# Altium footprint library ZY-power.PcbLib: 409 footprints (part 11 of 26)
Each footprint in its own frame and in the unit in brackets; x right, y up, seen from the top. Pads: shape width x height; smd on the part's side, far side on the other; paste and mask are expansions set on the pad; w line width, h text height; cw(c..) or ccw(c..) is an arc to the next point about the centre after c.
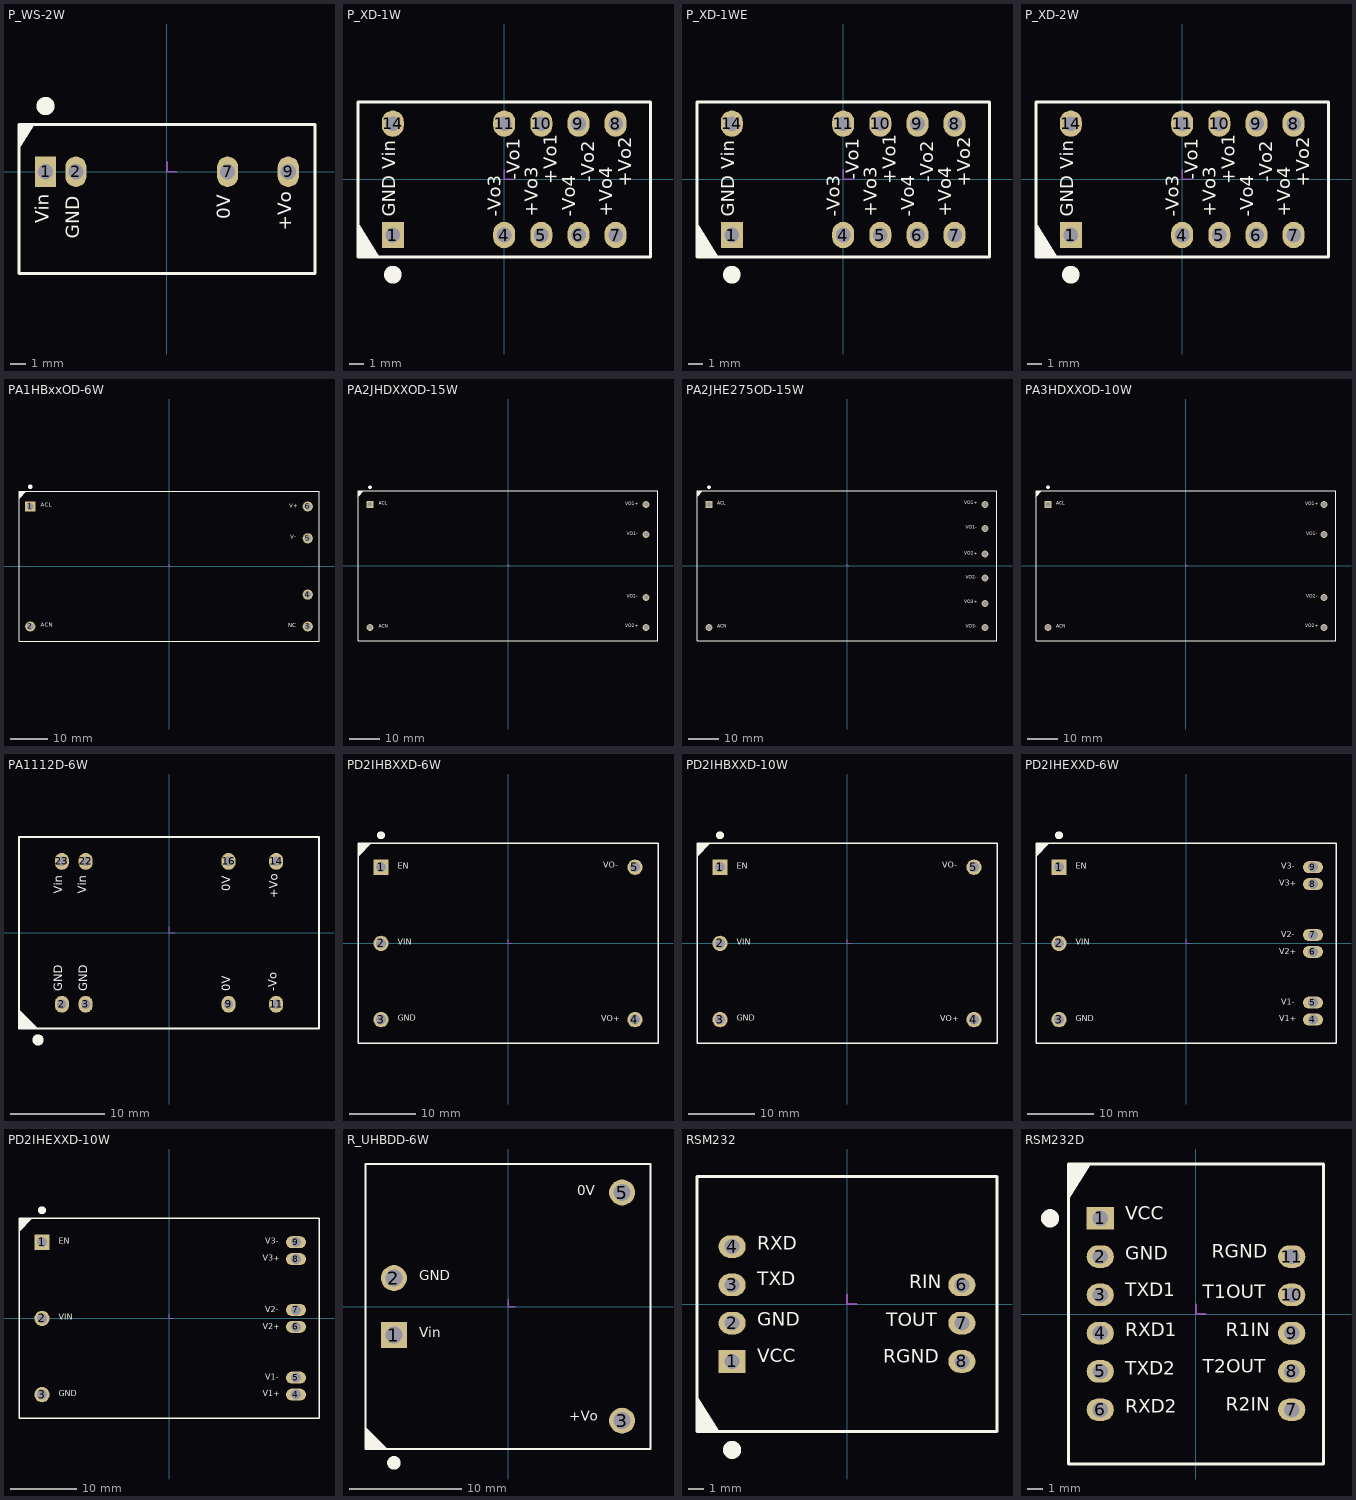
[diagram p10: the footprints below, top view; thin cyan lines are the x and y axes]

## P_WS-2W [mm]
height 12.5
pads (4):
  rect 1.4x2 hole 1: 1(-8,0)
  oval 1.4x2 hole 1: 2(-6,0) 7(4,0) 9(8,0)
Top Overlay:
  circle w1: c-8,4.325 r0.1
  region: -9.75,1.514 -9.75,3.1 -8.756,3.1
  lines w0.2: -9.75,-6.7 9.75,-6.7 9.75,3.1 -9.75,3.1 -9.75,-6.7
  text "Vin" at -7.492,-3.407 h1.52
  text "GND" at -5.475,-4.421 h1.52
  text "0V" at 4.48,-3.137 h1.52
  text "+Vo" at 8.5,-3.875 h1.52
Mechanical 15:
  lines w0.127: 0,0.635 0,0 0.635,0
3D body "zhenjao01.stp": height 8.36, standoff -4.08, extent 7.3,-1.48 8.7,0.12
3D body "zhenjao01.stp": height 8.36, standoff -4.08, extent 3.3,-1.48 4.7,0.12
3D body "zhenjao01.stp": height 8.36, standoff -4.08, extent -6.7,-1.48 -5.3,0.12
3D body "zhenjao01.stp": height 8.36, standoff -4.08, extent -8.7,-1.48 -7.3,0.12
3D body: height 12.5, standoff 0, extent -9.75,-6.7 9.75,3.1

## P_XD-1W [mm]
height 8.5
pads (10):
  rect 1.5x1.8 hole 1: 1(-7.62,-3.81)
  oval 1.5x1.8 hole 1: 4(0,-3.81) 5(2.54,-3.81) 6(5.08,-3.81) 7(7.62,-3.81) 8(7.62,3.81) 9(5.08,3.81) 10(2.54,3.81) 11(0,3.81) 14(-7.62,3.81)
Top Overlay:
  circle w1: c-7.62,-6.525 r0.1
  region: -10,-2.97 -10,-5.3 -8.54,-5.3
  lines w0.2: -10,-5.3 10,-5.3 10,5.3 -10,5.3 -10,-5.3
  text "GND" at -7.13,-2.562 h1.52
  text "Vin" at -7.138,0.699 h1.52
  text "-Vo3" at 0.074,-2.562 h1.52
  text "+Vo3" at 2.614,-2.562 h1.52
  text "+Vo4" at 7.694,-2.562 h1.52
  text "-Vo4" at 5.154,-2.562 h1.52
  text "+Vo2" at 8.994,-0.512 h1.52
  text "-Vo2" at 6.454,-0.202 h1.52
  text "-Vo1" at 1.374,-0.023 h1.52
  text "+Vo1" at 3.914,-0.333 h1.52
Mechanical 15:
  lines w0.127: 0,0.635 0,0 0.635,0
3D body: height 8.5, standoff 0, extent -10,-5.3 10,5.3
3D body: height 0, standoff -4.91, extent -7.843,-4.034 -7.395,-3.585
3D body: height 0, standoff -4.91, extent -7.843,3.586 -7.395,4.035
3D body: height 0, standoff -4.91, extent -0.223,-4.034 0.225,-3.585
3D body: height 0, standoff -4.91, extent 2.317,-4.034 2.765,-3.585
3D body: height 0, standoff -4.91, extent 4.857,-4.034 5.305,-3.585
3D body: height 0, standoff -4.91, extent 7.397,-4.034 7.845,-3.585
3D body: height 0, standoff -4.91, extent 7.397,3.586 7.845,4.035
3D body: height 0, standoff -4.91, extent 4.857,3.586 5.305,4.035
3D body: height 0, standoff -4.91, extent 2.317,3.586 2.765,4.035
3D body: height 0, standoff -4.91, extent -0.223,3.586 0.225,4.035

## P_XD-1WE [mm]
height 8.5
pads (10):
  rect 1.5x1.8 hole 1: 1(-7.62,-3.81)
  oval 1.5x1.8 hole 1: 4(0,-3.81) 5(2.54,-3.81) 6(5.08,-3.81) 7(7.62,-3.81) 8(7.62,3.81) 9(5.08,3.81) 10(2.54,3.81) 11(0,3.81) 14(-7.62,3.81)
Top Overlay:
  circle w1: c-7.62,-6.525 r0.1
  region: -10,-2.97 -10,-5.3 -8.54,-5.3
  lines w0.2: -10,-5.3 -10,5.3 10,5.3 10,-5.3 -10,-5.3
  text "+Vo1" at 3.914,-0.333 h1.52
  text "-Vo1" at 1.374,-0.023 h1.52
  text "-Vo2" at 6.454,-0.202 h1.52
  text "+Vo2" at 8.994,-0.512 h1.52
  text "-Vo4" at 5.154,-2.562 h1.52
  text "+Vo4" at 7.694,-2.562 h1.52
  text "+Vo3" at 2.614,-2.562 h1.52
  text "-Vo3" at 0.074,-2.562 h1.52
  text "Vin" at -7.138,0.699 h1.52
  text "GND" at -7.13,-2.562 h1.52
Mechanical 15:
  lines w0.127: 0,0.635 0,0 0.635,0
3D body: height 0, standoff -4.91, extent -0.223,3.586 0.225,4.035
3D body: height 0, standoff -4.91, extent 2.317,3.586 2.765,4.035
3D body: height 0, standoff -4.91, extent 4.857,3.586 5.305,4.035
3D body: height 0, standoff -4.91, extent 7.397,3.586 7.845,4.035
3D body: height 0, standoff -4.91, extent 7.397,-4.034 7.845,-3.585
3D body: height 0, standoff -4.91, extent 4.857,-4.034 5.305,-3.585
3D body: height 0, standoff -4.91, extent 2.317,-4.034 2.765,-3.585
3D body: height 0, standoff -4.91, extent -0.223,-4.034 0.225,-3.585
3D body: height 0, standoff -4.91, extent -7.843,3.586 -7.395,4.035
3D body: height 0, standoff -4.91, extent -7.843,-4.034 -7.395,-3.585
3D body: height 8.5, standoff 0, extent -10,-5.3 10,5.3

## P_XD-2W [mm]
height 8.5
pads (10):
  rect 1.5x1.8 hole 1: 1(-7.62,-3.81)
  oval 1.5x1.8 hole 1: 4(0,-3.81) 5(2.54,-3.81) 6(5.08,-3.81) 7(7.62,-3.81) 8(7.62,3.81) 9(5.08,3.81) 10(2.54,3.81) 11(0,3.81) 14(-7.62,3.81)
Top Overlay:
  circle w1: c-7.62,-6.525 r0.1
  region: -10,-2.97 -10,-5.3 -8.54,-5.3
  lines w0.2: -10,-5.3 -10,5.3 10,5.3 10,-5.3 -10,-5.3
  text "+Vo1" at 3.914,-0.333 h1.52
  text "-Vo1" at 1.374,-0.023 h1.52
  text "-Vo2" at 6.454,-0.202 h1.52
  text "+Vo2" at 8.994,-0.512 h1.52
  text "-Vo4" at 5.154,-2.562 h1.52
  text "+Vo4" at 7.694,-2.562 h1.52
  text "+Vo3" at 2.614,-2.562 h1.52
  text "-Vo3" at 0.074,-2.562 h1.52
  text "Vin" at -7.138,0.699 h1.52
  text "GND" at -7.13,-2.562 h1.52
Mechanical 15:
  lines w0.127: 0,0.635 0,0 0.635,0
3D body: height 0, standoff -4.91, extent -0.223,3.586 0.225,4.035
3D body: height 0, standoff -4.91, extent 2.317,3.586 2.765,4.035
3D body: height 0, standoff -4.91, extent 4.857,3.586 5.305,4.035
3D body: height 0, standoff -4.91, extent 7.397,3.586 7.845,4.035
3D body: height 0, standoff -4.91, extent 7.397,-4.034 7.845,-3.585
3D body: height 0, standoff -4.91, extent 4.857,-4.034 5.305,-3.585
3D body: height 0, standoff -4.91, extent 2.317,-4.034 2.765,-3.585
3D body: height 0, standoff -4.91, extent -0.223,-4.034 0.225,-3.585
3D body: height 0, standoff -4.91, extent -7.843,3.586 -7.395,4.035
3D body: height 0, standoff -4.91, extent -7.843,-4.034 -7.395,-3.585
3D body: height 8.5, standoff 0, extent -10,-5.3 10,5.3

## PA1HBxxOD-6W [mm]
pads (6):
  rect 2.7x2.7 hole 1.8: 1(-37,16)
  round 2.7 hole 1.8: 2(-37,-16) 3(37,-16) 4(37,-7.5) 5(37,7.5) 6(37,16)
Top Overlay:
  circle w1: c-37,21.225 r0.1
  region: -40,20 -40,18.025 -38.025,20
  lines w0.2: -40,-20 40,-20 40,20 -40,20 -40,-20
  text "ACL" at -34.206,15.494 h1.78
  text "ACN" at -34.206,-16.506 h1.78
  text "V+" at 32.01,15.24 h1.78
  text "V-" at 32.371,6.987 h1.78
  text "NC" at 31.791,-16.635 h1.78
Mechanical 15:
  lines w0.127: 0,0.635 0,0 0.635,0

## PA2JHDXXOD-15W [mm]
pads (6):
  rect 2.3x2.3 hole 1.5: 1(-46,20.5)
  round 2.3 hole 1.5: 2(-46,-20.5) 3(46,-20.5) 4(46,-10.5) 5(46,10.5) 6(46,20.5)
Top Overlay:
  circle w1: c-46,26.225 r0.1
  region: -50,25 -50,23.025 -48.025,25
  lines w0.2: -50,-25 -50,25 50,25 50,-25 -50,-25
  text "VO1+" at 39.142,19.779 h1.78
  text "VO1-" at 39.503,9.779 h1.78
  text "VO2-" at 39.503,-11.049 h1.78
  text "VO2+" at 39.142,-20.955 h1.78
  text "ACN" at -43.079,-21.061 h1.78
  text "ACL" at -43.079,19.939 h1.78
Mechanical 15:
  lines w0.127: 0,0.635 0,0 0.635,0

## PA2JHE275OD-15W [mm]
pads (8):
  rect 2.3x2.3 hole 1.8: 1(-46,20.5)
  round 2.3 hole 1.8: 2(-46,-20.5) 3(46,-20.5) 4(46,-12.5) 5(46,-4) 6(46,4) 7(46,12.5) 8(46,20.5)
Top Overlay:
  circle w1: c-46,26.225 r0.1
  region: -50,25 -50,23.025 -48.025,25
  lines w0.2: -50,-25 -50,25 50,25 50,-25 -50,-25
  text "VO2-" at 39.503,-4.699 h1.78
  text "VO2+" at 39.142,3.302 h1.78
  text "VO1+" at 39.142,20.033 h1.78
  text "VO1-" at 39.503,11.938 h1.78
  text "VO3-" at 39.503,-21.082 h1.78
  text "VO3+" at 39.142,-12.954 h1.78
  text "ACN" at -43.333,-21.061 h1.78
  text "ACL" at -43.333,19.939 h1.78
Mechanical 15:
  lines w0.127: 0,0.635 0,0 0.635,0

## PA3HDXXOD-10W [mm]
pads (6):
  rect 2.3x2.3 hole 1.8: 1(-46,20.5)
  round 2.3 hole 1.8: 2(-46,-20.5) 3(46,-20.5) 4(46,-10.5) 5(46,10.5) 6(46,20.5)
Top Overlay:
  circle w1: c-46,26.225 r0.1
  region: -50,25 -50,23.025 -48.025,25
  lines w0.2: -50,-25 50,-25 50,25 -50,25 -50,-25
  text "ACL" at -43.206,19.939 h1.78
  text "ACN" at -43.206,-21.061 h1.78
  text "VO2+" at 39.777,-20.955 h1.78
  text "VO2-" at 40.086,-11.049 h1.78
  text "VO1-" at 40.086,9.779 h1.78
  text "VO1+" at 39.777,19.779 h1.78
Mechanical 15:
  lines w0.127: 0,0.635 0,0 0.635,0

## PA1112D-6W [mm]
height 10.3
pads (8):
  oval 1.5x1.8 hole 1: 2(-11.43,-7.62) 3(-8.89,-7.62) 9(6.35,-7.62) 11(11.43,-7.62) 14(11.43,7.62) 16(6.35,7.62) 22(-8.89,7.62) 23(-11.43,7.62)
Top Overlay:
  circle w1: c-13.97,-11.425 r0.1
  region: -16,-10.2 -14.025,-10.2 -16,-8.225
  lines w0.2: -16,-10.2 -16,10.2 16,10.2 16,-10.2 -16,-10.2
  text "GND" at -11.049,-6.223 h1.52
  text "GND" at -8.382,-6.223 h1.52
  text "Vin" at -11.049,4.151 h1.52
  text "Vin" at -8.509,4.151 h1.52
  text "-Vo" at 11.811,-6.223 h1.52
  text "+Vo" at 11.938,3.683 h1.52
  text "0V" at 6.858,4.423 h1.52
  text "0V" at 6.833,-6.223 h1.52
Mechanical 15:
  lines w0.127: 0,0.635 0,0 0.635,0

## PD2IHBXXD-6W [mm]
pads (5):
  rect 2.3x2.3 hole 1.5: 1(-19.05,11.43)
  round 2.3 hole 1.5: 2(-19.05,0) 3(-19.05,-11.43) 4(19.05,-11.43) 5(19.05,11.43)
Top Overlay:
  circle w1: c-19.05,16.225 r0.1
  region: -22.5,15 -22.5,13.025 -20.525,15
  lines w0.2: -22.5,-15 22.5,-15 22.5,15 -22.5,15 -22.5,-15
  text "VO-" at 14.279,11.049 h1.52
  text "VO+" at 13.97,-11.938 h1.52
  text "GND" at -16.511,-11.936 h1.52
  text "VIN" at -16.51,-0.506 h1.52
  text "EN" at -16.511,10.924 h1.52
Mechanical 15:
  lines w0.127: 0,0.635 0,0 0.635,0

## PD2IHBXXD-10W [mm]
pads (5):
  rect 2.3x2.3 hole 1.5: 1(-19.05,11.43)
  round 2.3 hole 1.5: 2(-19.05,0) 3(-19.05,-11.43) 4(19.05,-11.43) 5(19.05,11.43)
Top Overlay:
  circle w1: c-19.05,16.225 r0.1
  region: -22.5,15 -22.5,13.025 -20.525,15
  lines w0.2: -22.5,-15 22.5,-15 22.5,15 -22.5,15 -22.5,-15
  text "VO-" at 14.279,11.049 h1.52
  text "VO+" at 13.97,-11.938 h1.52
  text "GND" at -16.511,-11.936 h1.52
  text "VIN" at -16.51,-0.506 h1.52
  text "EN" at -16.511,10.924 h1.52
Mechanical 15:
  lines w0.127: 0,0.635 0,0 0.635,0

## PD2IHEXXD-6W [mm]
pads (9):
  rect 2.3x2.3 hole 1.5 unplated: 1(-19.05,11.43)
  round 2.3 hole 1.5 unplated: 2(-19.05,0) 3(-19.05,-11.43)
  oval 3x1.8 hole 1.5 unplated: 4(19.05,-11.43) 5(19.05,-8.89) 6(19.05,-1.27) 7(19.05,1.27) 8(19.05,8.89) 9(19.05,11.43)
Top Overlay:
  circle w1: c-19.05,16.225 r0.1
  region: -22.5,15 -22.5,13.025 -20.525,15
  lines w0.2: -22.5,-15 22.5,-15 22.5,15 -22.5,15 -22.5,-15
  text "EN" at -16.511,10.922 h1.52
  text "VIN" at -16.51,-0.508 h1.52
  text "GND" at -16.511,-11.938 h1.52
  text "V1+" at 13.97,-11.938 h1.52
  text "V1-" at 14.279,-9.525 h1.52
  text "V2+" at 13.97,-1.905 h1.52
  text "V2-" at 14.279,0.635 h1.52
  text "V3+" at 13.97,8.382 h1.52
  text "V3-" at 14.279,10.922 h1.52
Mechanical 15:
  lines w0.127: 0,0.635 0,0 0.635,0

## PD2IHEXXD-10W [mm]
pads (9):
  rect 2.3x2.3 hole 1.5 unplated: 1(-19.05,11.43)
  round 2.3 hole 1.5 unplated: 2(-19.05,0) 3(-19.05,-11.43)
  oval 3x1.8 hole 1.5 unplated: 4(19.05,-11.43) 5(19.05,-8.89) 6(19.05,-1.27) 7(19.05,1.27) 8(19.05,8.89) 9(19.05,11.43)
Top Overlay:
  circle w1: c-19.05,16.225 r0.1
  region: -22.5,15 -22.5,13.025 -20.525,15
  lines w0.2: -22.5,-15 22.5,-15 22.5,15 -22.5,15 -22.5,-15
  text "EN" at -16.511,10.922 h1.52
  text "VIN" at -16.51,-0.508 h1.52
  text "GND" at -16.511,-11.938 h1.52
  text "V1+" at 14.097,-11.938 h1.52
  text "V1-" at 14.406,-9.525 h1.52
  text "V2+" at 14.097,-1.905 h1.52
  text "V2-" at 14.406,0.635 h1.52
  text "V3+" at 14.097,8.382 h1.52
  text "V3-" at 14.406,10.922 h1.52
Mechanical 15:
  lines w0.127: 0,0.635 0,0 0.635,0

## R_UHBDD-6W [mm]
height 11.8
pads (4):
  rect 2.3x2.3 hole 1.5: 1(-10.16,-2.54)
  round 2.3 hole 1.5: 2(-10.16,2.54) 3(10.16,-10.16) 5(10.16,10.16)
Top Overlay:
  circle w1: c-10.16,-13.925 r0.1
  region: -12.7,-12.7 -10.725,-12.7 -12.7,-10.725
  lines w0.2: -12.7,-12.7 -12.7,12.7 12.7,12.7 12.7,-12.7 -12.7,-12.7
  text "GND" at -7.901,2.05 h1.52
  text "Vin" at -7.9,-3.025 h1.52
  text "+Vo" at 5.435,-10.5 h1.52
  text "0V" at 6.175,9.625 h1.52
Mechanical 15:
  lines w0.127: 0,0.635 0,0 0.635,0
3D body: height 11.8, standoff 0, extent -12.7,-12.7 12.7,12.7
3D body: height -1.1, standoff -6.01, extent -10.656,2.041 -9.66,3.039
3D body: height -1.1, standoff -6.01, extent -10.656,-3.039 -9.66,-2.041
3D body: height -1.1, standoff -6.01, extent 9.664,-10.659 10.66,-9.661
3D body: height -1.1, standoff -6.01, extent 9.664,9.661 10.66,10.659

## RSM232 [mm]
height 7.1
pads (7):
  rect 1.8x1.5 hole 1: 1(-7.62,-3.81)
  oval 1.8x1.5 hole 1: 2(-7.62,-1.27) 3(-7.62,1.27) 4(-7.62,3.81) 6(7.62,1.27) 7(7.62,-1.27) 8(7.62,-3.81)
Top Overlay:
  circle w1: c-7.62,-9.675 r0.1
  region: -9.95,-6.12 -9.95,-8.45 -8.49,-8.45
  lines w0.2: -9.95,-8.45 9.95,-8.45 9.95,8.45 -9.95,8.45 -9.95,-8.45
  text "RIN" at 4.116,0.762 h1.52
  text "TOUT" at 2.597,-1.778 h1.52
  text "VCC" at -5.969,-4.166 h1.52
  text "GND" at -5.969,-1.753 h1.52
  text "TXD" at -5.969,0.94 h1.52
  text "RXD" at -5.969,3.302 h1.52
  text "RGND" at 2.413,-4.191 h1.52
Mechanical 15:
  lines w0.127: 0,0.635 0,0 0.635,0
3D body: height 7.1, standoff 0, extent -9.95,-8.45 9.95,8.45
3D body "zhen01.stp": height 6.09, standoff -4.41, extent -7.87,3.56 -7.37,4.06
3D body "zhen01.stp": height 6.09, standoff -4.41, extent -7.87,1.02 -7.37,1.52
3D body "zhen01.stp": height 6.09, standoff -4.41, extent -7.87,-1.52 -7.37,-1.02
3D body "zhen01.stp": height 6.09, standoff -4.41, extent -7.87,-4.06 -7.37,-3.56
3D body "zhen01.stp": height 6.09, standoff -4.41, extent 7.37,-4.06 7.87,-3.56
3D body "zhen01.stp": height 6.09, standoff -4.41, extent 7.37,-1.52 7.87,-1.02
3D body "zhen01.stp": height 6.09, standoff -4.41, extent 7.37,1.02 7.87,1.52

## RSM232D [mm]
height 7.05
pads (11):
  rect 1.8x1.5 hole 1: 1(-6.35,6.35)
  oval 1.8x1.5 hole 1: 2(-6.35,3.81) 3(-6.35,1.27) 4(-6.35,-1.27) 5(-6.35,-3.81) 6(-6.35,-6.35) 7(6.35,-6.35) 8(6.35,-3.81) 9(6.35,-1.27) 10(6.35,1.27) 11(6.35,3.81)
Top Overlay:
  circle w1: c-9.675,6.35 r0.1
  region: -8.45,7.62 -8.45,9.95 -6.99,9.95
  lines w0.2: -8.45,-9.95 -8.45,9.95 8.45,9.95 8.45,-9.95 -8.45,-9.95
  text "RGND" at 1.032,3.429 h1.52
  text "T1OUT" at 0.458,0.762 h1.52
  text "VCC" at -4.699,5.969 h1.52
  text "GND" at -4.7,3.302 h1.52
  text "TXD1" at -4.7,0.889 h1.52
  text "RXD1" at -4.7,-1.778 h1.52
  text "R1IN" at 1.977,-1.778 h1.52
  text "T2OUT" at 0.458,-4.191 h1.52
  text "R2IN" at 1.977,-6.731 h1.52
  text "TXD2" at -4.7,-4.318 h1.52
  text "RXD2" at -4.7,-6.858 h1.52
Mechanical 15:
  lines w0.127: 0,0.635 0,0 0.635,0
3D body: height 7.1, standoff 0, extent -8.45,-9.95 8.45,9.95
3D body "zhen01.stp": height 6.09, standoff -4.41, extent -6.6,6.1 -6.1,6.6
3D body "zhen01.stp": height 6.09, standoff -4.41, extent -6.6,3.56 -6.1,4.06
3D body "zhen01.stp": height 6.09, standoff -4.41, extent -6.6,1.02 -6.1,1.52
3D body "zhen01.stp": height 6.09, standoff -4.41, extent -6.6,-1.52 -6.1,-1.02
3D body "zhen01.stp": height 6.09, standoff -4.41, extent -6.6,-4.06 -6.1,-3.56
3D body "zhen01.stp": height 6.09, standoff -4.41, extent -6.6,-6.6 -6.1,-6.1
3D body "zhen01.stp": height 6.09, standoff -4.41, extent 6.1,-6.6 6.6,-6.1
3D body "zhen01.stp": height 6.09, standoff -4.41, extent 6.1,-4.06 6.6,-3.56
3D body "zhen01.stp": height 6.09, standoff -4.41, extent 6.1,-1.52 6.6,-1.02
3D body "zhen01.stp": height 6.09, standoff -4.41, extent 6.1,1.02 6.6,1.52
3D body "zhen01.stp": height 6.09, standoff -4.41, extent 6.1,3.56 6.6,4.06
